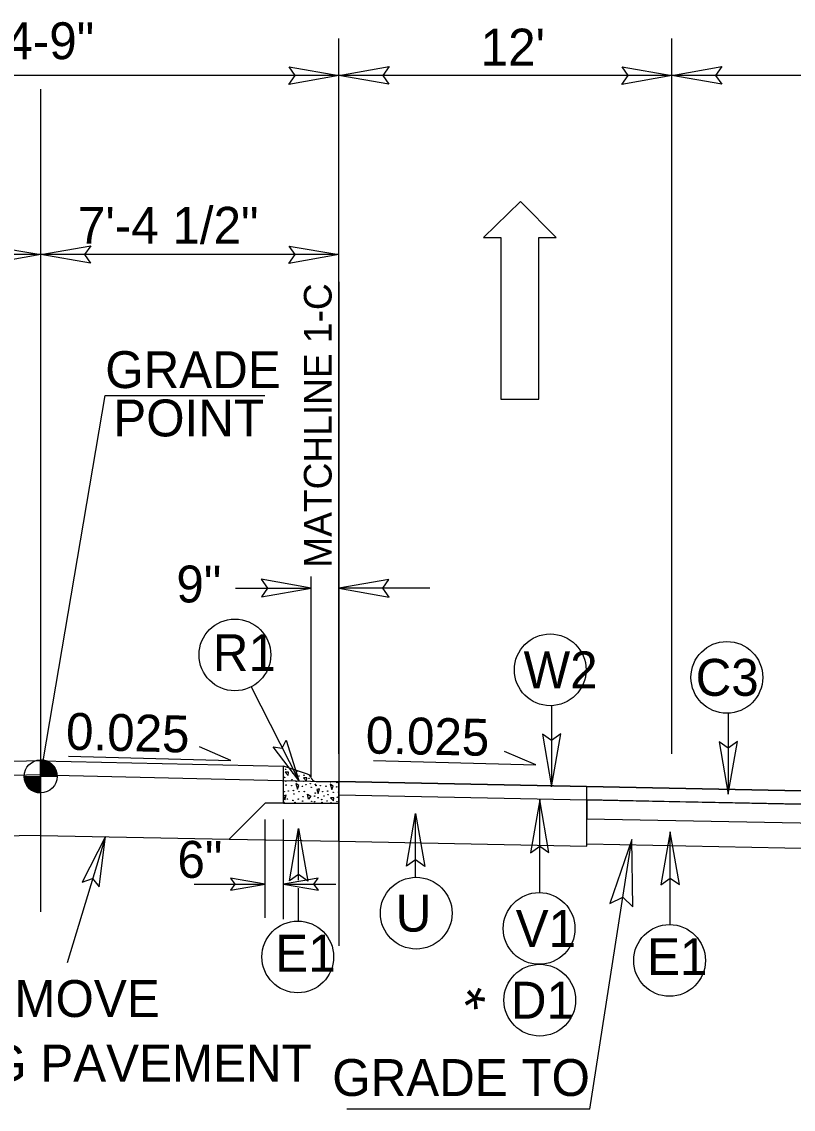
# Model space of a CAD drawing. Extents: x 2320980 to 2456309, y 595047 to 606177.
# Drawn here: x 2455902.76 to 2455930.57, y 597311.37 to 597350.58 of the extents above; entities that cross this region are included whole.
import ezdxf

# ---------------------------------------------------------------- set-up
doc = ezdxf.new("R2010")
doc.units = 0
for name, color, linetype in [('Matchline', 7, 'Continuous'), ('Matchline Text', 7, 'Continuous'), ('Old_Level_1', 7, 'Continuous'), ('Old_Level_11', 7, 'Continuous'), ('Old_Level_20', 7, 'Continuous'), ('Old_Level_21', 7, 'Continuous'), ('Old_Level_3', 7, 'Continuous'), ('Prop Dimension Text', 7, 'Continuous'), ('Prop Lane Arrow CELL', 7, 'Continuous'), ('Prop Terminator CELL', 7, 'Continuous'), ('Typical Grade Point Symbol CELL', 7, 'Continuous'), ('Typical ID Circle CELL', 7, 'Continuous'), ('Typical Pavement Slope CELL', 7, 'Continuous'), ('Typical Terminator CELL', 7, 'Continuous')]:
    doc.layers.add(name, color=color, linetype=linetype)

msp = doc.modelspace()

# ---------------------------------------------------------------- linework, layer by layer
at = {"layer": 'Matchline'}
msp.add_line((2455914.194, 597341.198), (2455914.194, 597317.258), dxfattribs=at)
at = {"layer": 'Old_Level_1'}
for p, q in [((2455903.442, 597323.368), (2455905.763, 597337.097)), ((2455905.763, 597337.097), (2455911.52, 597337.097)), ((2455912.199, 597322.405), (2455912.199, 597323.735)), ((2455913.063, 597323.446), (2455912.199, 597323.735)), ((2455912.375, 597323.518), (2455912.26, 597323.518)), ((2455912.26, 597323.518), (2455912.369, 597323.403)), ((2455912.369, 597323.403), (2455912.375, 597323.518)), ((2455913.031, 597323.311), (2455912.915, 597323.311)), ((2455912.915, 597323.311), (2455913.024, 597323.195)), ((2455913.024, 597323.195), (2455913.031, 597323.311)), ((2455912.641, 597323.111), (2455912.697, 597322.91)), ((2455912.752, 597323.033), (2455912.641, 597323.111)), ((2455912.697, 597322.91), (2455912.752, 597323.033)), ((2455913.373, 597323.18), (2455914.194, 597323.18)), ((2455913.491, 597322.918), (2455913.394, 597322.9)), ((2455913.443, 597322.754), (2455913.491, 597322.918)), ((2455913.877, 597323.09), (2455913.933, 597322.891)), ((2455913.987, 597323.012), (2455913.877, 597323.09)), ((2455913.933, 597322.891), (2455913.987, 597323.012)), ((2455914.194, 597322.405), (2455914.194, 597323.18)), ((2455923.129, 597320.85), (2455923.129, 597323.002)), ((2455912.296, 597322.687), (2455912.199, 597322.668)), ((2455912.199, 597322.668), (2455912.248, 597322.522)), ((2455912.248, 597322.522), (2455912.296, 597322.687)), ((2455913.055, 597322.723), (2455913.176, 597322.656)), ((2455913.098, 597322.547), (2455913.055, 597322.723)), ((2455913.176, 597322.656), (2455913.098, 597322.547)), ((2455913.394, 597322.9), (2455913.443, 597322.754)), ((2455914.01, 597322.598), (2455913.894, 597322.598)), ((2455913.894, 597322.598), (2455914.003, 597322.482)), ((2455914.003, 597322.482), (2455914.01, 597322.598)), ((2455912.199, 597322.405), (2455914.194, 597322.405)), ((2455903.444, 597321.24), (2455896.666, 597321.105)), ((2455903.444, 597321.24), (2455910.234, 597321.105)), ((2455914.194, 597321.027), (2455923.129, 597320.85))]:
    msp.add_line(p, q, dxfattribs=at)
for centre in [(2455912.233, 597323.329), (2455912.268, 597323.618), (2455912.459, 597323.634), (2455912.553, 597323.465), (2455912.671, 597323.543), (2455912.751, 597323.379), (2455912.933, 597323.409), (2455913.119, 597323.296), (2455912.277, 597323.197), (2455912.289, 597323.051), (2455912.49, 597323.033), (2455912.496, 597323.252), (2455912.654, 597323.185), (2455912.878, 597323.009), (2455912.909, 597323.191), (2455913, 597323.069), (2455913.164, 597323.106), (2455913.194, 597322.972), (2455913.346, 597323.075), (2455913.367, 597323.036), (2455913.513, 597323.176), (2455913.525, 597323.03), (2455913.725, 597323.012), (2455913.889, 597323.164), (2455914.114, 597322.988), (2455914.125, 597323.139), (2455912.228, 597322.817), (2455912.338, 597322.553), (2455912.368, 597322.839), (2455912.551, 597322.857), (2455912.569, 597322.729), (2455912.728, 597322.547), (2455912.751, 597322.814), (2455912.903, 597322.638), (2455912.945, 597322.82), (2455913.316, 597322.656), (2455913.337, 597322.763), (2455913.442, 597322.594), (2455913.573, 597322.532), (2455913.604, 597322.818), (2455913.654, 597322.662), (2455913.786, 597322.836), (2455913.804, 597322.708), (2455913.986, 597322.793), (2455914.138, 597322.617), (2455914.181, 597322.799), (2455912.532, 597322.499), (2455912.607, 597322.432), (2455912.884, 597322.474), (2455913.212, 597322.468), (2455913.316, 597322.45), (2455913.585, 597322.432), (2455913.768, 597322.477), (2455913.908, 597322.421), (2455914.12, 597322.453)]:
    msp.add_circle(centre, 0.00853, dxfattribs=at)
for centre, radius, start, end in [((2455913.001, 597323.263), 0.194, 16.7189, 71.565), ((2455913.373, 597323.375), 0.194, 196.7189, 270), ((2455912.223, 597322.414), 0.00853, 27.0386, 154.2416)]:
    msp.add_arc(centre, radius, start, end, dxfattribs=at)
at = {"layer": 'Old_Level_11'}
msp.add_lwpolyline([(2455924.791, 597318.664), (2455924.752, 597321.093), (2455923.96, 597318.78), (2455924.429, 597319.017)], close=True, dxfattribs=at)
at = {"layer": 'Old_Level_21'}
for p, q in [((2455914.194, 597324.179), (2455914.194, 597349.968)), ((2455926.194, 597324.179), (2455926.194, 597349.968)), ((2455914.194, 597348.638), (2455892.694, 597348.638)), ((2455940.854, 597348.638), (2455912.754, 597348.638)), ((2455903.444, 597342.179), (2455892.694, 597342.179)), ((2455914.194, 597342.179), (2455903.444, 597342.179)), ((2455913.196, 597323.323), (2455913.196, 597330.57)), ((2455910.466, 597330.153), (2455913.196, 597330.153)), ((2455917.469, 597330.153), (2455914.194, 597330.153)), ((2455911.534, 597318.268), (2455911.534, 597321.812)), ((2455912.199, 597318.221), (2455912.199, 597321.812)), ((2455923.236, 597311.365), (2455924.752, 597321.093)), ((2455914.48, 597311.377), (2455923.238, 597311.377))]:
    msp.add_line(p, q, dxfattribs=at)
at = {"layer": 'Old_Level_3'}
for p, q in [((2455914.194, 597322.696), (2455938.194, 597322.222)), ((2455923.129, 597321.84), (2455938.194, 597321.542))]:
    msp.add_line(p, q, dxfattribs=at)
at = {"layer": 'Prop Dimension Text'}
for p, q in [((2455903.444, 597338.354), (2455903.444, 597348.147)), ((2455903.444, 597318.483), (2455903.444, 597338.354)), ((2455911.027, 597326.593), (2455912.743, 597323.216)), ((2455905.776, 597321.194), (2455904.393, 597316.646)), ((2455908.972, 597319.481), (2455911.534, 597319.481)), ((2455912.199, 597319.481), (2455914.085, 597319.481))]:
    msp.add_line(p, q, dxfattribs=at)
for points in [[(2455904.443, 597324.102), (2455910.299, 597323.941), (2455909.163, 597324.43)], [(2455915.438, 597323.942), (2455921.294, 597323.781), (2455920.157, 597324.269)]]:
    msp.add_lwpolyline(points, dxfattribs=at)
for centre in [(2455910.443, 597327.746), (2455921.808, 597327.208), (2455928.175, 597326.937), (2455916.979, 597318.435), (2455921.408, 597317.884), (2455912.709, 597316.857), (2455926.11, 597316.73), (2455921.431, 597315.298)]:
    msp.add_circle(centre, 1.293, dxfattribs=at)
at = {"layer": 'Prop Lane Arrow CELL'}
for p, q in [((2455920.734, 597344.1), (2455919.404, 597342.791)), ((2455922.022, 597342.791), (2455920.734, 597344.1)), ((2455919.404, 597342.791), (2455920.027, 597342.791)), ((2455920.027, 597342.791), (2455920.027, 597336.972)), ((2455921.399, 597336.972), (2455921.399, 597342.791)), ((2455921.399, 597342.791), (2455922.022, 597342.791)), ((2455920.027, 597336.972), (2455921.399, 597336.972))]:
    msp.add_line(p, q, dxfattribs=at)
at = {"layer": 'Prop Terminator CELL'}
msp.add_lwpolyline([(2455905.549, 597319.381), (2455905.776, 597321.194), (2455904.943, 597319.555), (2455905.316, 597319.682)], close=True, dxfattribs=at)
at = {"layer": 'Typical Grade Point Symbol CELL'}
for p, q in [((2455903.442, 597323.368), (2455903.442, 597323.964)), ((2455902.847, 597323.368), (2455903.442, 597323.368)), ((2455903.441, 597322.773), (2455903.442, 597323.368)), ((2455903.442, 597323.368), (2455903.441, 597322.773)), ((2455904.038, 597323.368), (2455903.442, 597323.368))]:
    msp.add_line(p, q, dxfattribs=at)
for points in [[(2455903.448, 597323.964), (2455903.448, 597323.964), (2455903.448, 597323.368)], [(2455903.459, 597323.964), (2455903.459, 597323.368)], [(2455903.471, 597323.962), (2455903.471, 597323.368)], [(2455903.483, 597323.962), (2455903.483, 597323.368)], [(2455903.495, 597323.961), (2455903.495, 597323.368)], [(2455903.507, 597323.96), (2455903.507, 597323.368)], [(2455903.519, 597323.958), (2455903.519, 597323.368)], [(2455903.531, 597323.957), (2455903.531, 597323.368)], [(2455903.543, 597323.956), (2455903.543, 597323.368)], [(2455903.555, 597323.953), (2455903.555, 597323.368)], [(2455903.567, 597323.95), (2455903.567, 597323.368)], [(2455903.579, 597323.948), (2455903.579, 597323.368)], [(2455903.59, 597323.945), (2455903.59, 597323.368)], [(2455903.602, 597323.941), (2455903.602, 597323.368)], [(2455903.614, 597323.938), (2455903.614, 597323.368)], [(2455903.626, 597323.935), (2455903.626, 597323.368)], [(2455903.638, 597323.931), (2455903.638, 597323.368)], [(2455903.65, 597323.927), (2455903.65, 597323.368)], [(2455903.662, 597323.921), (2455903.662, 597323.368)], [(2455903.674, 597323.916), (2455903.674, 597323.368)], [(2455903.686, 597323.911), (2455903.686, 597323.368)], [(2455903.698, 597323.905), (2455903.698, 597323.368)], [(2455903.71, 597323.9), (2455903.71, 597323.368)], [(2455903.721, 597323.894), (2455903.721, 597323.368)], [(2455903.733, 597323.887), (2455903.733, 597323.368)], [(2455903.745, 597323.88), (2455903.745, 597323.368)], [(2455903.757, 597323.874), (2455903.757, 597323.368)], [(2455903.769, 597323.866), (2455903.769, 597323.368)], [(2455903.781, 597323.858), (2455903.781, 597323.368)], [(2455903.793, 597323.849), (2455903.793, 597323.368)], [(2455903.805, 597323.841), (2455903.805, 597323.368)], [(2455903.817, 597323.831), (2455903.817, 597323.368)], [(2455903.829, 597323.821), (2455903.829, 597323.368)], [(2455903.84, 597323.81), (2455903.84, 597323.368)], [(2455903.852, 597323.8), (2455903.852, 597323.368)], [(2455903.864, 597323.788), (2455903.864, 597323.368)], [(2455903.876, 597323.776), (2455903.876, 597323.368)], [(2455903.888, 597323.763), (2455903.888, 597323.368)], [(2455903.9, 597323.748), (2455903.9, 597323.368)], [(2455903.912, 597323.733), (2455903.912, 597323.368)], [(2455903.924, 597323.718), (2455903.924, 597323.368)], [(2455903.936, 597323.7), (2455903.936, 597323.368)], [(2455902.85, 597323.368), (2455902.85, 597323.303)], [(2455902.862, 597323.368), (2455902.862, 597323.233)], [(2455902.873, 597323.368), (2455902.873, 597323.191)], [(2455902.885, 597323.368), (2455902.885, 597323.155)], [(2455902.897, 597323.368), (2455902.897, 597323.128)], [(2455902.909, 597323.368), (2455902.909, 597323.102)], [(2455902.921, 597323.368), (2455902.921, 597323.08)], [(2455902.933, 597323.368), (2455902.933, 597323.059)], [(2455902.945, 597323.368), (2455902.945, 597323.04)], [(2455902.957, 597323.368), (2455902.957, 597323.023)], [(2455902.969, 597323.368), (2455902.969, 597323.007)], [(2455902.981, 597323.368), (2455902.981, 597322.993)], [(2455902.992, 597323.368), (2455902.992, 597322.978)], [(2455903.004, 597323.368), (2455903.004, 597322.965)], [(2455903.016, 597323.368), (2455903.016, 597322.952)], [(2455903.028, 597323.368), (2455903.028, 597322.94)], [(2455903.04, 597323.368), (2455903.04, 597322.929)], [(2455903.052, 597323.368), (2455903.052, 597322.919)], [(2455903.064, 597323.368), (2455903.064, 597322.908)], [(2455903.076, 597323.368), (2455903.076, 597322.899)], [(2455903.088, 597323.368), (2455903.088, 597322.889)], [(2455903.1, 597323.368), (2455903.1, 597322.882)], [(2455903.112, 597323.368), (2455903.112, 597322.874)], [(2455903.123, 597323.368), (2455903.123, 597322.866)], [(2455903.135, 597323.368), (2455903.135, 597322.858)], [(2455903.147, 597323.368), (2455903.147, 597322.851)], [(2455903.159, 597323.368), (2455903.159, 597322.845)], [(2455903.171, 597323.368), (2455903.171, 597322.838)], [(2455903.183, 597323.368), (2455903.183, 597322.833)], [(2455903.195, 597323.368), (2455903.195, 597322.827)], [(2455903.207, 597323.368), (2455903.207, 597322.822)], [(2455903.219, 597323.368), (2455903.219, 597322.817)], [(2455903.231, 597323.368), (2455903.231, 597322.811)], [(2455903.243, 597323.368), (2455903.243, 597322.807)], [(2455903.254, 597323.368), (2455903.254, 597322.804)], [(2455903.266, 597323.368), (2455903.266, 597322.799)], [(2455903.278, 597323.368), (2455903.278, 597322.797)], [(2455903.29, 597323.368), (2455903.29, 597322.793)], [(2455903.302, 597323.368), (2455903.302, 597322.79)], [(2455903.314, 597323.368), (2455903.314, 597322.788)], [(2455903.326, 597323.368), (2455903.326, 597322.785)], [(2455903.338, 597323.368), (2455903.338, 597322.782)], [(2455903.35, 597323.368), (2455903.35, 597322.781)], [(2455903.362, 597323.368), (2455903.362, 597322.778)], [(2455903.373, 597323.368), (2455903.373, 597322.777)], [(2455903.385, 597323.368), (2455903.385, 597322.776)], [(2455903.397, 597323.368), (2455903.397, 597322.774)], [(2455903.409, 597323.368), (2455903.409, 597322.774)], [(2455903.421, 597323.368), (2455903.421, 597322.773)], [(2455903.433, 597323.368), (2455903.433, 597322.773), (2455903.433, 597322.773)], [(2455903.948, 597323.682), (2455903.948, 597323.368)], [(2455903.959, 597323.662), (2455903.959, 597323.368)], [(2455903.971, 597323.641), (2455903.971, 597323.368)], [(2455903.983, 597323.616), (2455903.983, 597323.368)], [(2455903.995, 597323.588), (2455903.995, 597323.368)], [(2455904.007, 597323.555), (2455904.007, 597323.368)], [(2455904.019, 597323.514), (2455904.019, 597323.368)], [(2455904.031, 597323.453), (2455904.031, 597323.368)]]:
    msp.add_lwpolyline(points, dxfattribs=at)
msp.add_circle((2455903.442, 597323.368), 0.595, dxfattribs=at)
for start, end in [(359.9905, 89.9905), (179.9905, 269.9905)]:
    msp.add_arc((2455903.442, 597323.368), 0.595, start, end, dxfattribs=at)
at = {"layer": 'Typical ID Circle CELL'}
for p, q in [((2455921.858, 597325.936), (2455921.858, 597322.995)), ((2455928.225, 597325.664), (2455928.225, 597322.724)), ((2455921.434, 597319.181), (2455921.434, 597322.519)), ((2455916.954, 597319.733), (2455916.954, 597322.024)), ((2455912.735, 597319.622), (2455912.735, 597321.492)), ((2455926.136, 597318.027), (2455926.136, 597321.366)), ((2455912.735, 597318.154), (2455912.735, 597319.336))]:
    msp.add_line(p, q, dxfattribs=at)
at = {"layer": 'Typical Pavement Slope CELL'}
for p, q in [((2455903.444, 597323.929), (2455894.689, 597323.729)), ((2455903.444, 597323.931), (2455912.199, 597323.731)), ((2455903.444, 597323.419), (2455892.694, 597323.174)), ((2455903.444, 597323.421), (2455914.194, 597323.176)), ((2455914.194, 597323.18), (2455938.194, 597322.7)), ((2455914.194, 597321.027), (2455914.194, 597323.18)), ((2455938.194, 597322.7), (2455914.194, 597323.18)), ((2455914.194, 597323.18), (2455914.194, 597322.696)), ((2455914.194, 597322.696), (2455938.194, 597322.222)), ((2455927.037, 597322.442), (2455923.129, 597322.519)), ((2455923.129, 597322.519), (2455923.129, 597321.84)), ((2455911.534, 597322.405), (2455910.234, 597321.105)), ((2455912.199, 597322.405), (2455911.534, 597322.405)), ((2455938.194, 597322.222), (2455927.142, 597322.44)), ((2455923.129, 597321.84), (2455938.194, 597321.542)), ((2455910.234, 597321.105), (2455914.194, 597321.027)), ((2455923.129, 597320.936), (2455943.143, 597320.536))]:
    msp.add_line(p, q, dxfattribs=at)
msp.add_lwpolyline([(2455927.142, 597322.44), (2455927.037, 597322.442)], dxfattribs=at)
at = {"layer": 'Typical Terminator CELL'}
for points in [[(2455912.398, 597348.947), (2455914.194, 597348.638), (2455912.388, 597348.318), (2455912.617, 597348.638)], [(2455915.989, 597348.328), (2455914.194, 597348.638), (2455915.999, 597348.957), (2455915.77, 597348.638)], [(2455924.398, 597348.947), (2455926.194, 597348.638), (2455924.388, 597348.318), (2455924.617, 597348.638)], [(2455927.989, 597348.328), (2455926.194, 597348.638), (2455927.999, 597348.957), (2455927.77, 597348.638)], [(2455901.648, 597342.488), (2455903.444, 597342.179), (2455901.638, 597341.86), (2455901.867, 597342.179)], [(2455905.239, 597341.87), (2455903.444, 597342.179), (2455905.249, 597342.498), (2455905.02, 597342.179)], [(2455912.398, 597342.488), (2455914.194, 597342.179), (2455912.388, 597341.86), (2455912.617, 597342.179)], [(2455911.401, 597329.844), (2455913.196, 597330.153), (2455911.391, 597330.473), (2455911.62, 597330.153)], [(2455915.989, 597330.463), (2455914.194, 597330.153), (2455915.999, 597329.834), (2455915.77, 597330.153)], [(2455921.532, 597324.89), (2455921.858, 597322.995), (2455922.195, 597324.901), (2455921.858, 597324.658)], [(2455912.295, 597324.667), (2455912.743, 597323.216), (2455911.825, 597324.437), (2455912.148, 597324.387)], [(2455927.899, 597324.618), (2455928.225, 597322.724), (2455928.562, 597324.629), (2455928.225, 597324.387)], [(2455921.76, 597320.624), (2455921.434, 597322.519), (2455921.097, 597320.614), (2455921.434, 597320.856)], [(2455916.628, 597320.129), (2455916.954, 597322.024), (2455917.291, 597320.118), (2455916.954, 597320.36)], [(2455912.408, 597319.597), (2455912.735, 597321.492), (2455913.072, 597319.587), (2455912.735, 597319.829)], [(2455926.462, 597319.471), (2455926.136, 597321.366), (2455925.799, 597319.46), (2455926.136, 597319.702)], [(2455910.287, 597319.267), (2455911.534, 597319.481), (2455910.28, 597319.703), (2455910.439, 597319.481)], [(2455913.445, 597319.696), (2455912.199, 597319.481), (2455913.452, 597319.26), (2455913.293, 597319.481)]]:
    msp.add_lwpolyline(points, close=True, dxfattribs=at)

# ---------------------------------------------------------------- texts
at = {"layer": 'Matchline Text'}
msp.add_text('MATCHLINE 1-C', height=1, rotation=90, dxfattribs=at).set_placement((2455913.93, 597330.891))
at = {"layer": 'Old_Level_1'}
for s, p in [('GRADE', (2455905.77, 597337.368)), ('POINT', (2455906.06, 597335.625))]:
    msp.add_text(s, height=1.33, dxfattribs=at).set_placement(p)
at = {"layer": 'Old_Level_20'}
for s, p in [('R1', (2455909.647, 597327.162)), ('W2', (2455920.849, 597326.543)), ('C3', (2455927.05, 597326.272)), ('U', (2455916.238, 597317.77)), ('V1', (2455920.564, 597317.219)), ('E1', (2455911.898, 597316.327)), ('E1', (2455925.299, 597316.201)), ('D1', (2455920.39, 597314.633))]:
    msp.add_text(s, height=1.33, dxfattribs=at).set_placement(p)
at = {"layer": 'Old_Level_21'}
for s, p in [('14-9"', (2455901.182, 597349.226)), ("12'", (2455919.303, 597348.996)), ('7\'-4 1/2"', (2455904.787, 597342.572)), ('9"', (2455908.334, 597329.639)), ('6"', (2455908.372, 597319.709)), ('REMOVE ', (2455900.025, 597314.692)), ('EXISTING PAVEMENT', (2455894.635, 597312.364)), ('GRADE TO', (2455913.951, 597311.844))]:
    msp.add_text(s, height=1.33, dxfattribs=at).set_placement(p)
for rotation, p in [(358.5846, (2455904.343, 597324.333)), (358.8544, (2455915.15, 597324.194))]:
    msp.add_text('0.025', height=1.33, rotation=rotation, dxfattribs=at).set_placement(p)
at = {"layer": 'Typical Pavement Slope CELL'}
msp.add_text('*', height=1.496, rotation=333.4341, dxfattribs=at).set_placement((2455918.255, 597314.551))

doc.saveas('drawing.dxf')
